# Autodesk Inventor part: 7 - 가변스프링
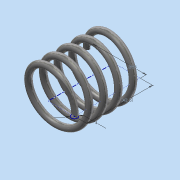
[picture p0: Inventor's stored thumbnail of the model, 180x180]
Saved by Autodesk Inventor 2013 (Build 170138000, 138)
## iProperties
Created: 2015-03
Part Number: 7 - 가변스프링
Material: 강철, 탄소
Document SubType Name: Modeling
Designer: Administrator
Density: 7.87 g/cm^3
Mass: 48.0346 g
Surface Area: 61.9996 cm^2
Volume: 6.1035 cm^3
Author: Administrator
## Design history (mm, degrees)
sketch "스케치1"
  geometry: L1 (0, 0)-(17.5, 0); L2 (17.5, 0)-(17.5, 43.5); L3 (17.5, 43.5)-(0, 43.5); L4 (0, 43.5)-(0, 0); C1 r 2 at (17.5, 0)
  constraints: 8 end point, 2 parallel, 1 centre point, 1 coincident, 1 horizontal, 1 perpendicular
  dimensions: "d0" = 4 diameter of C1; "d2" = 35 diameter of L2 L4; "d3" = 43.5 distance of L1.end L2.end (derived)
feature "코일1" sketch "스케치1" pitch "d4" = 10; turns "d6" = 4.5; dims "d5" = 43.5 (= d3), "d7" = 0, angle "d8" = 90 deg, angle "d9" = 90 deg, "d10" = 0, "d11" = 0
node "작업 평면1"
sketch "스케치2"
  geometry: L1 (-15.5, 0)-(-19.5, 0) reference; L2 (-15.5, 0)-(-19.5, 0) reference; 1 further point
  constraints: 2 horizontal alignment
extrude "돌출1" cut sketch "스케치2" stored distance "d13" = 10; taper "d14" = 0 deg
node "작업 평면2"
sketch "스케치3"
  geometry: L1 (19.5, 0)-(15.5, 0) reference; 1 further point
  constraints: 1 horizontal alignment
extrude "돌출2" cut sketch "스케치3" stored distance "d16" = 10; taper "d17" = 0 deg
node "솔리드1"
node "절단 모서리 투영1"
node "절단 모서리 투영2"
node "절단 모서리 투영3"
other parameters: "d12" = 0, "d15" = 43.5 (= d3)
